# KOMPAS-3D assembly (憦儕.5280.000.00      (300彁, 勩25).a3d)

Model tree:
1. Плоскость XY
2. Плоскость ZX
3. Плоскость ZY
4. Ось X
5. Ось Y
6. Ось Z
7. Начало координат  (labels: Операция без истории:1; Операция без истории:2; Операция без истории:3; Импортированная поверхность:1)

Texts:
  Линия-выноска #1
  Линия-выноска #2
  Линия-выноска #3
  Отклонения формы и база
  Марка координационной оси
  Марка/позиционное обозначение с линией-выноской
  Марка/позиционное обозначение на линии
  Марка/позиционное обозначение без линии-выноски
